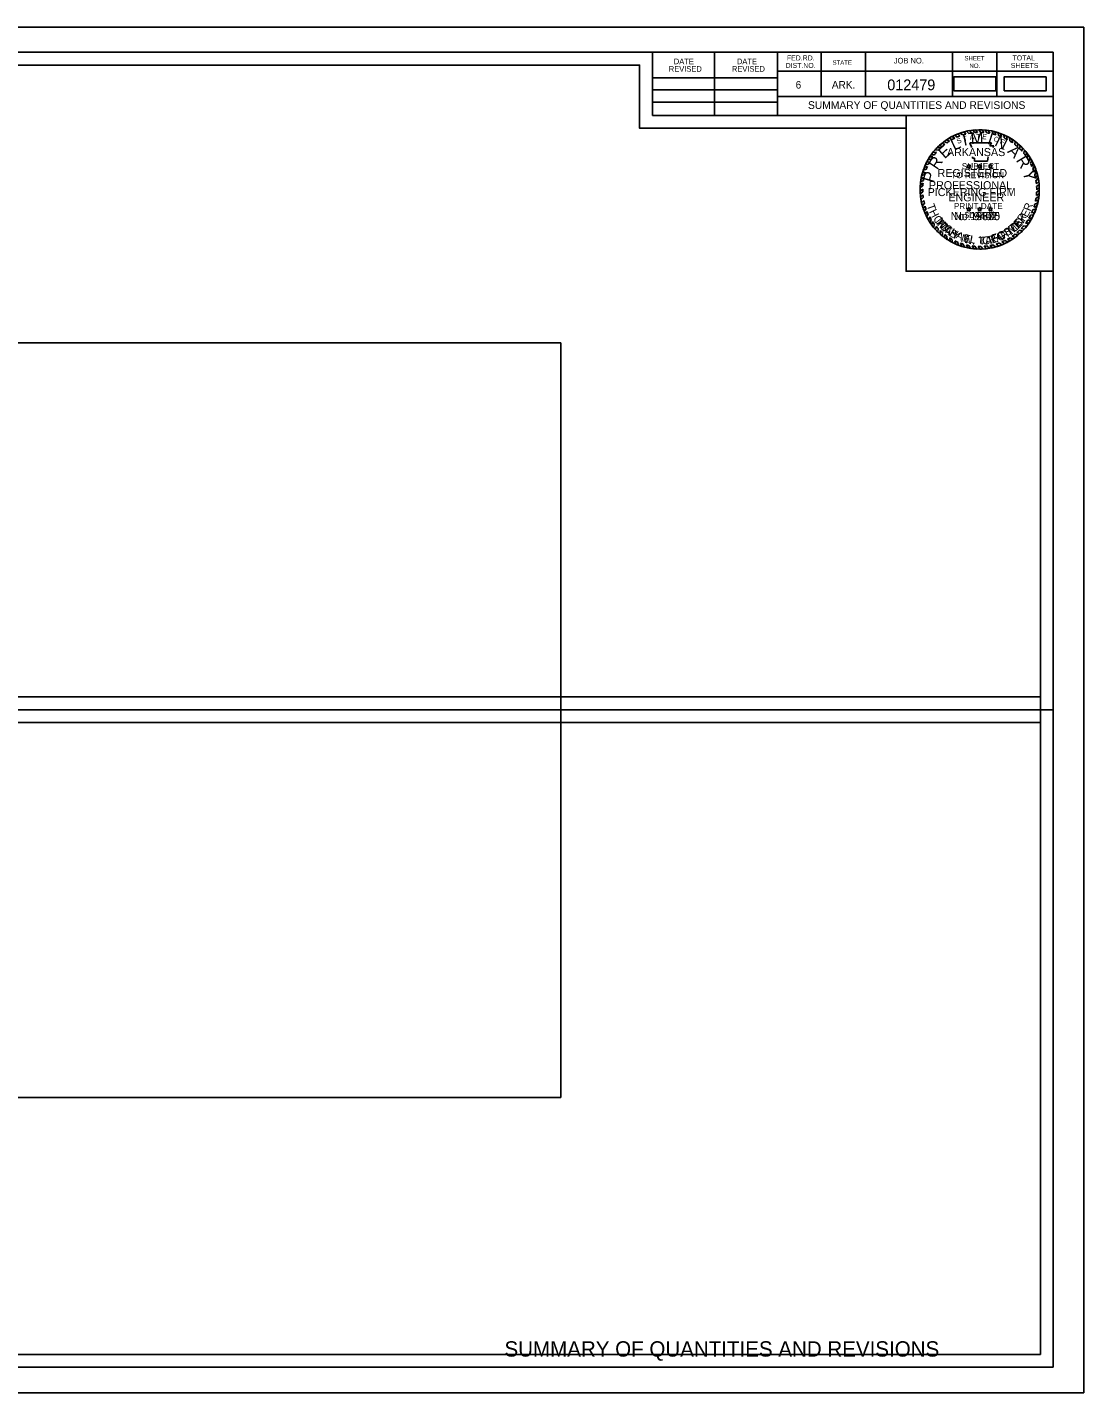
# Model space of a CAD drawing. Extents: x 1369290 to 1371547, y 379683 to 379897.
# Drawn here: x 1371381.5 to 1371546.5, y 379683.5 to 379896.8 of the extents above; entities that cross this region are included whole.
import ezdxf

# ---------------------------------------------------------------- set-up
doc = ezdxf.new("R2010")
doc.units = 0
for name, color, linetype in [('Default', 7, 'Continuous'), ('R_Border', 7, 'Continuous'), ('R_Border Notes', 7, 'Continuous'), ('R_Border Plan-Plan', 7, 'Continuous'), ('R_Border Title', 7, 'Continuous'), ('R_No Plot', 7, 'Continuous'), ('STAMP_PE_CRAFTON', 7, 'Continuous'), ('STAMP_PE_FOSTER', 7, 'Continuous'), ('STAMP_PE_SEAL-INFO', 7, 'Continuous'), ('STAMP_PE_TAEGTMEYER', 7, 'Continuous'), ('STAMP_PE_TXT', 7, 'Continuous'), ('STAMP_PRELIMINARY', 7, 'Continuous')]:
    doc.layers.add(name, color=color, linetype=linetype)

msp = doc.modelspace()

# ---------------------------------------------------------------- linework, layer by layer
at = {"layer": 'Default'}
for points in [[(1371526.23, 379886.89), (1371532.79, 379886.89), (1371532.79, 379889.08), (1371526.23, 379889.08)], [(1371534.1, 379886.89), (1371540.66, 379886.89), (1371540.66, 379889.08), (1371534.1, 379889.08)], [(1371294.91, 379729.63), (1371464.81, 379729.63), (1371464.81, 379847.52), (1371294.91, 379847.52)]]:
    msp.add_lwpolyline(points, close=True, dxfattribs=at)
at = {"layer": 'R_Border'}
for p, q in [((1371225.6, 379892.93), (1371541.78, 379892.93)), ((1371479.14, 379883.05), (1371479.14, 379892.93)), ((1371488.82, 379883.05), (1371488.82, 379892.93)), ((1371498.68, 379892.93), (1371498.68, 379883.05)), ((1371505.52, 379892.93), (1371505.52, 379885.99)), ((1371512.46, 379892.93), (1371512.46, 379885.99)), ((1371526.04, 379892.93), (1371526.04, 379885.99)), ((1371532.98, 379892.93), (1371532.98, 379885.99)), ((1371541.78, 379687.47), (1371541.78, 379892.93)), ((1371479.14, 379888.91), (1371498.68, 379888.91)), ((1371541.78, 379889.99), (1371498.68, 379889.99)), ((1371541.78, 379890.01), (1371541.78, 379890.01)), ((1371479.14, 379887.05), (1371498.68, 379887.05)), ((1371479.14, 379885.11), (1371498.68, 379885.11)), ((1371541.78, 379885.99), (1371498.68, 379885.99)), ((1371501.64, 379885.99), (1371541.78, 379885.99)), ((1371541.78, 379883.05), (1371479.14, 379883.05)), ((1371541.78, 379687.47), (1371225.6, 379687.47))]:
    msp.add_line(p, q, dxfattribs=at)
at = {"layer": 'R_Border Plan-Plan'}
msp.add_line((1371225.6, 379790.2), (1371541.78, 379790.2), dxfattribs=at)
at = {"layer": 'R_No Plot'}
for points in [[(1371213.19, 379896.82), (1371546.53, 379896.82), (1371546.53, 379683.48), (1371213.19, 379683.48)], [(1371539.78, 379792.2), (1371227.6, 379792.2), (1371227.6, 379890.93), (1371477.14, 379890.93), (1371477.14, 379881.05), (1371494.68, 379881.05), (1371518.78, 379881.05), (1371518.78, 379858.71), (1371539.78, 379858.71)], [(1371227.6, 379890.93), (1371477.14, 379890.93), (1371477.14, 379881.05), (1371494.68, 379881.05), (1371518.78, 379881.05), (1371518.78, 379858.71), (1371539.78, 379858.71), (1371539.78, 379689.47), (1371227.6, 379689.47)], [(1371518.78, 379883.05), (1371541.78, 379883.05), (1371541.78, 379858.71), (1371518.78, 379858.71)], [(1371227.6, 379788.2), (1371539.78, 379788.2), (1371539.78, 379689.47), (1371227.6, 379689.47)]]:
    msp.add_lwpolyline(points, close=True, dxfattribs=at)
at = {"layer": 'STAMP_PE_SEAL-INFO'}
for p, q in [((1371525.95, 379879.75), (1371526.42, 379879.52)), ((1371526.38, 379879.96), (1371526.77, 379879.68)), ((1371526.89, 379880.18), (1371527.19, 379879.85)), ((1371527.24, 379880.3), (1371527.62, 379880)), ((1371527.83, 379880.49), (1371528.12, 379880.14)), ((1371528.22, 379880.58), (1371528.57, 379880.24)), ((1371528.7, 379880.68), (1371529, 379880.31)), ((1371529.22, 379880.75), (1371529.5, 379880.37)), ((1371529.95, 379880.4), (1371529.64, 379880.79)), ((1371530.45, 379880.4), (1371530.17, 379880.81)), ((1371530.91, 379880.38), (1371530.65, 379880.81)), ((1371531.41, 379880.33), (1371531.12, 379880.77)), ((1371531.84, 379880.27), (1371531.58, 379880.72)), ((1371532.4, 379880.15), (1371532.23, 379880.61)), ((1371532.8, 379880.04), (1371532.64, 379880.51)), ((1371533.26, 379879.89), (1371533.11, 379880.37)), ((1371533.67, 379879.73), (1371533.53, 379880.23)), ((1371534.13, 379879.53), (1371534.03, 379880.02)), ((1371534.58, 379879.3), (1371534.49, 379879.81)), ((1371523.32, 379877.69), (1371523.84, 379877.65)), ((1371523.64, 379878.04), (1371524.19, 379877.99)), ((1371523.98, 379878.36), (1371524.44, 379878.22)), ((1371524.32, 379878.66), (1371524.85, 379878.56)), ((1371524.7, 379878.99), (1371525.15, 379878.78)), ((1371525.12, 379879.25), (1371525.56, 379879.05)), ((1371525.51, 379879.5), (1371525.94, 379879.27)), ((1371528.75, 379878.78), (1371532.1, 379878.78)), ((1371528.87, 379878.47), (1371528.75, 379878.78)), ((1371528.98, 379878.18), (1371528.87, 379878.47)), ((1371528.99, 379878.06), (1371528.98, 379878.18)), ((1371532.1, 379878.78), (1371531.87, 379878.29)), ((1371531.87, 379878.29), (1371532.51, 379878.29)), ((1371532.51, 379878.29), (1371532.36, 379878.06)), ((1371534.97, 379879.07), (1371534.93, 379879.57)), ((1371535.4, 379878.78), (1371535.37, 379879.3)), ((1371535.76, 379878.52), (1371535.8, 379879)), ((1371536.21, 379878.15), (1371536.23, 379878.67)), ((1371536.52, 379877.85), (1371536.59, 379878.35)), ((1371536.88, 379877.48), (1371536.95, 379878.01)), ((1371537.16, 379877.16), (1371537.29, 379877.63)), ((1371521.8, 379875.35), (1371522.3, 379875.46)), ((1371521.98, 379875.74), (1371522.48, 379875.81)), ((1371522.22, 379876.17), (1371522.7, 379876.19)), ((1371522.46, 379876.57), (1371522.98, 379876.6)), ((1371522.7, 379876.91), (1371523.2, 379876.91)), ((1371522.97, 379877.28), (1371523.52, 379877.3)), ((1371529.18, 379876.35), (1371529.15, 379876.57)), ((1371529.49, 379876.35), (1371529.18, 379876.35)), ((1371529.49, 379875.92), (1371529.49, 379876.35)), ((1371531.52, 379875.92), (1371529.49, 379875.92)), ((1371531.54, 379876.26), (1371531.52, 379875.92)), ((1371531.61, 379876.57), (1371531.54, 379876.26)), ((1371537.48, 379876.75), (1371537.61, 379877.25)), ((1371537.7, 379876.43), (1371537.88, 379876.89)), ((1371538.01, 379875.93), (1371538.19, 379876.42)), ((1371538.21, 379875.57), (1371538.43, 379876.01)), ((1371538.44, 379875.08), (1371538.66, 379875.57)), ((1371521.56, 379873.36), (1371521.1, 379873.11)), ((1371521.2, 379873.6), (1371521.67, 379873.8)), ((1371521.31, 379874.01), (1371521.78, 379874.18)), ((1371521.46, 379874.51), (1371521.95, 379874.65)), ((1371521.61, 379874.92), (1371522.12, 379875.07)), ((1371538.58, 379874.75), (1371538.84, 379875.18)), ((1371538.77, 379874.2), (1371539.04, 379874.67)), ((1371538.88, 379873.83), (1371539.17, 379874.28)), ((1371539.01, 379873.27), (1371539.33, 379873.72)), ((1371539.08, 379872.89), (1371539.44, 379873.25)), ((1371521.38, 379872.04), (1371520.96, 379871.78)), ((1371521.37, 379871.55), (1371520.96, 379871.21)), ((1371521.42, 379872.46), (1371520.98, 379872.18)), ((1371521.37, 379871.14), (1371520.98, 379870.81)), ((1371521.48, 379872.9), (1371521.03, 379872.68)), ((1371539.15, 379872.38), (1371539.52, 379872.72)), ((1371539.18, 379871.97), (1371539.57, 379872.26)), ((1371539.18, 379871.04), (1371539.6, 379871.32)), ((1371539.19, 379871.45), (1371539.6, 379871.77)), ((1371521.41, 379870.64), (1371521.04, 379870.29)), ((1371521.46, 379870.21), (1371521.1, 379869.84)), ((1371521.54, 379869.75), (1371521.2, 379869.39)), ((1371521.63, 379869.34), (1371521.32, 379868.92)), ((1371538.89, 379869.2), (1371539.37, 379869.4)), ((1371539, 379869.65), (1371539.46, 379869.84)), ((1371539.09, 379870.15), (1371539.54, 379870.37)), ((1371539.14, 379870.54), (1371539.58, 379870.79)), ((1371521.76, 379868.89), (1371521.46, 379868.47)), ((1371521.9, 379868.47), (1371521.61, 379868.05)), ((1371522.06, 379868.04), (1371521.8, 379867.62)), ((1371522.23, 379867.66), (1371522.01, 379867.19)), ((1371522.47, 379867.2), (1371522.28, 379866.71)), ((1371537.96, 379866.97), (1371538.47, 379867.03)), ((1371538.24, 379867.47), (1371538.73, 379867.54)), ((1371538.4, 379867.81), (1371538.89, 379867.9)), ((1371538.61, 379868.32), (1371539.09, 379868.45)), ((1371538.75, 379868.7), (1371539.24, 379868.9)), ((1371522.7, 379866.79), (1371522.52, 379866.32)), ((1371522.91, 379866.48), (1371522.8, 379865.93)), ((1371523.19, 379866.09), (1371523.09, 379865.56)), ((1371523.49, 379865.71), (1371523.4, 379865.19)), ((1371523.79, 379865.38), (1371523.73, 379864.85)), ((1371524.12, 379865.05), (1371524.09, 379864.52)), ((1371524.46, 379864.74), (1371524.46, 379864.21)), ((1371536.1, 379864.74), (1371536.57, 379864.61)), ((1371536.51, 379865.11), (1371536.95, 379864.97)), ((1371536.76, 379865.37), (1371537.24, 379865.29)), ((1371537.15, 379865.8), (1371537.61, 379865.73)), ((1371537.45, 379866.2), (1371537.96, 379866.2)), ((1371537.79, 379866.69), (1371538.27, 379866.69)), ((1371524.82, 379864.44), (1371524.84, 379863.92)), ((1371525.16, 379864.19), (1371525.2, 379863.68)), ((1371525.59, 379863.91), (1371525.65, 379863.4)), ((1371525.94, 379863.71), (1371526.03, 379863.19)), ((1371526.42, 379863.46), (1371526.57, 379862.94)), ((1371526.79, 379863.29), (1371526.96, 379862.78)), ((1371527.28, 379863.1), (1371527.49, 379862.59)), ((1371527.69, 379862.96), (1371527.92, 379862.47)), ((1371528.2, 379862.82), (1371528.41, 379862.36)), ((1371528.6, 379862.74), (1371528.84, 379862.28)), ((1371529.1, 379862.66), (1371529.34, 379862.21)), ((1371529.53, 379862.61), (1371529.81, 379862.18)), ((1371530.02, 379862.58), (1371530.32, 379862.17)), ((1371530.48, 379862.58), (1371530.82, 379862.18)), ((1371531, 379862.61), (1371531.32, 379862.23)), ((1371531.44, 379862.65), (1371531.81, 379862.29)), ((1371531.88, 379862.72), (1371532.27, 379862.38)), ((1371532.37, 379862.83), (1371532.75, 379862.5)), ((1371532.83, 379862.95), (1371533.25, 379862.65)), ((1371533.33, 379863.11), (1371533.77, 379862.84)), ((1371533.75, 379863.28), (1371534.17, 379863.02)), ((1371534.2, 379863.49), (1371534.69, 379863.28)), ((1371534.61, 379863.7), (1371535.03, 379863.47)), ((1371535.03, 379863.95), (1371535.48, 379863.75)), ((1371535.37, 379864.17), (1371535.81, 379863.98)), ((1371535.83, 379864.52), (1371536.3, 379864.37))]:
    msp.add_line(p, q, dxfattribs=at)
for radius, start, end in [(9.32, 117.6544, 120.8099), (9.32, 111.3124, 114.7026), (8.91, 110.3086, 113.1659), (9.32, 105.2339, 109.0352), (8.91, 104.0352, 107.3615), (9.32, 99.7525, 102.7765), (8.91, 98.258, 101.0329), (9.32, 93.9381, 96.5517), (8.91, 92.1102, 95.0367), (9.32, 87.7298, 90.6707), (8.91, 85.9628, 88.9097), (9.32, 81.9732, 84.8236), (8.91, 79.9264, 82.696), (9.32, 75.3125, 77.9426), (8.91, 73.5575, 76.2314), (9.32, 69.6061, 72.3058), (8.91, 67.6248, 70.504), (9.32, 63.1329, 66.2704), (9.32, 135.4021, 138.3031), (8.91, 133.1331, 136.2562), (9.32, 129.7326, 132.5376), (8.91, 127.5297, 130.9683), (9.32, 123.6199, 126.5906), (8.91, 121.9746, 125.11), (8.91, 115.6869, 119.1583), (8.91, 61.1558, 64.3784), (9.32, 56.9003, 60.0942), (8.91, 54.9238, 58.2702), (8.91, 48.3016, 52.0395), (9.32, 50.3492, 53.7159), (8.91, 42.2212, 45.5512), (9.32, 44.3405, 47.3929), (9.32, 38.1247, 41.2316), (9.32, 152.864, 155.5189), (9.32, 147.0072, 149.899), (8.91, 151.0315, 153.573), (9.32, 141.6056, 144.4486), (8.91, 145.0197, 148.2104), (8.91, 139.301, 142.5873), (8.91, 36.135, 39.5311), (8.91, 29.9032, 33.6645), (9.32, 31.9614, 35.4294), (8.91, 23.7732, 27.2211), (9.32, 25.9391, 29.0125), (9.32, 164.3068, 166.894), (9.32, 158.4077, 161.0701), (8.91, 167.9048, 170.9039), (8.91, 162.4331, 165.0013), (8.91, 156.3402, 159.2319), (8.91, 17.6802, 21.4251), (9.32, 19.9538, 23.3141), (8.91, 11.5444, 15.2364), (9.32, 13.8421, 17.4447), (9.32, 7.5852, 10.8621), (9.32, 175.7409, 178.2066), (9.32, 181.7251, 184.1626), (9.32, 170.0003, 172.6878), (8.91, 179.6454, 182.2633), (8.91, 173.73, 176.4734), (8.91, 5.7599, 9.0606), (8.91, 359.7329, 3.0639), (9.32, 1.7215, 4.7268), (9.32, 355.7156, 358.9569), (9.32, 187.4204, 190.1927), (9.32, 193.0369, 195.9973), (8.91, 185.4539, 188.234), (8.91, 191.2274, 193.9858), (8.91, 341.777, 345.0925), (8.91, 348.0778, 351.3435), (8.91, 353.8632, 357.1274), (9.32, 343.8925, 347.035), (9.32, 349.8305, 353.0885), (9.32, 198.8967, 201.6281), (8.91, 196.9675, 199.8353), (9.32, 204.5479, 207.4328), (8.91, 202.7761, 205.4791), (8.91, 208.7883, 211.7934), (8.91, 329.5549, 333.2076), (8.91, 335.6038, 339.1858), (9.32, 331.4037, 334.9332), (9.32, 337.3837, 340.9933), (9.32, 210.8636, 213.6571), (9.32, 216.6115, 219.491), (8.91, 214.1838, 217.2747), (9.32, 222.48, 225.3801), (8.91, 220.3909, 223.3056), (8.91, 226.2494, 229.2407), (8.91, 310.7744, 314.3161), (9.32, 312.4518, 315.6633), (8.91, 316.6531, 320.3711), (9.32, 318.2846, 321.8043), (8.91, 323.5851, 327.4407), (9.32, 325.4405, 328.9872), (9.32, 228.3665, 231.348), (8.91, 232.229, 234.9336), (9.32, 234.295, 236.9452), (8.91, 238.2223, 240.8353), (9.32, 240.1977, 242.8613), (8.91, 244.3204, 246.9486), (9.32, 246.576, 249.1558), (8.91, 250.3491, 253.1216), (9.32, 252.5967, 255.3252), (8.91, 256.505, 259.1192), (8.91, 262.3783, 265.2012), (8.91, 268.3215, 271.277), (8.91, 274.6157, 277.4486), (8.91, 280.3459, 283.5814), (8.91, 286.6423, 289.9783), (9.32, 288.5709, 291.9733), (8.91, 292.8745, 296.1185), (9.32, 294.6481, 298.2166), (8.91, 299.0768, 302.1724), (9.32, 300.621, 303.8703), (8.91, 304.823, 308.5143), (9.32, 306.3721, 310.208), (9.32, 258.4433, 261.1398), (9.32, 264.1978, 267.1009), (9.32, 270.2548, 273.3361), (9.32, 276.4239, 279.4357), (9.32, 282.3199, 285.3702)]:
    msp.add_arc((1371530.28, 379871.49), radius, start, end, dxfattribs=at)
at = {"layer": 'STAMP_PE_TXT'}
for p, q in [((1371528.51, 379875.21), (1371528.58, 379875.44)), ((1371528.58, 379875.44), (1371528.66, 379875.21)), ((1371530.2, 379875.21), (1371530.28, 379875.44)), ((1371530.28, 379875.44), (1371530.36, 379875.21)), ((1371531.9, 379875.21), (1371531.98, 379875.44)), ((1371531.98, 379875.44), (1371532.05, 379875.21)), ((1371528.46, 379875.06), (1371528.26, 379875.21)), ((1371528.26, 379875.21), (1371528.51, 379875.21)), ((1371528.38, 379874.83), (1371528.46, 379875.06)), ((1371528.58, 379874.97), (1371528.38, 379874.83)), ((1371528.78, 379874.83), (1371528.58, 379874.97)), ((1371528.66, 379875.21), (1371528.9, 379875.21)), ((1371528.9, 379875.21), (1371528.71, 379875.06)), ((1371528.71, 379875.06), (1371528.78, 379874.83)), ((1371530.16, 379875.06), (1371529.96, 379875.21)), ((1371529.96, 379875.21), (1371530.2, 379875.21)), ((1371530.08, 379874.83), (1371530.16, 379875.06)), ((1371530.28, 379874.97), (1371530.08, 379874.83)), ((1371530.48, 379874.83), (1371530.28, 379874.97)), ((1371530.36, 379875.21), (1371530.6, 379875.21)), ((1371530.6, 379875.21), (1371530.4, 379875.06)), ((1371530.4, 379875.06), (1371530.48, 379874.83)), ((1371531.86, 379875.06), (1371531.66, 379875.21)), ((1371531.66, 379875.21), (1371531.9, 379875.21)), ((1371531.78, 379874.83), (1371531.86, 379875.06)), ((1371531.98, 379874.97), (1371531.78, 379874.83)), ((1371532.18, 379874.83), (1371531.98, 379874.97)), ((1371532.05, 379875.21), (1371532.3, 379875.21)), ((1371532.3, 379875.21), (1371532.1, 379875.06)), ((1371532.1, 379875.06), (1371532.18, 379874.83)), ((1371528.46, 379868.35), (1371528.26, 379868.5)), ((1371528.26, 379868.5), (1371528.51, 379868.5)), ((1371528.38, 379868.12), (1371528.46, 379868.35)), ((1371528.58, 379868.27), (1371528.38, 379868.12)), ((1371528.51, 379868.5), (1371528.58, 379868.73)), ((1371528.58, 379868.73), (1371528.66, 379868.5)), ((1371528.78, 379868.12), (1371528.58, 379868.27)), ((1371528.66, 379868.5), (1371528.9, 379868.5)), ((1371528.9, 379868.5), (1371528.71, 379868.35)), ((1371528.71, 379868.35), (1371528.78, 379868.12)), ((1371530.16, 379868.35), (1371529.96, 379868.5)), ((1371529.96, 379868.5), (1371530.2, 379868.5)), ((1371530.08, 379868.12), (1371530.16, 379868.35)), ((1371530.28, 379868.27), (1371530.08, 379868.12)), ((1371530.2, 379868.5), (1371530.28, 379868.73)), ((1371530.28, 379868.73), (1371530.36, 379868.5)), ((1371530.48, 379868.12), (1371530.28, 379868.27)), ((1371530.36, 379868.5), (1371530.6, 379868.5)), ((1371530.6, 379868.5), (1371530.4, 379868.35)), ((1371530.4, 379868.35), (1371530.48, 379868.12)), ((1371531.86, 379868.35), (1371531.66, 379868.5)), ((1371531.66, 379868.5), (1371531.9, 379868.5)), ((1371531.78, 379868.12), (1371531.86, 379868.35)), ((1371531.98, 379868.27), (1371531.78, 379868.12)), ((1371531.9, 379868.5), (1371531.98, 379868.73)), ((1371531.98, 379868.73), (1371532.05, 379868.5)), ((1371532.18, 379868.12), (1371531.98, 379868.27)), ((1371532.05, 379868.5), (1371532.3, 379868.5)), ((1371532.3, 379868.5), (1371532.1, 379868.35)), ((1371532.1, 379868.35), (1371532.18, 379868.12))]:
    msp.add_line(p, q, dxfattribs=at)
at = {"layer": 'STAMP_PRELIMINARY'}
msp.add_circle((1371530.28, 379871.49), 9.32, dxfattribs=at)

# ---------------------------------------------------------------- texts
at = {"layer": 'R_Border'}
for s, height, p in [('FED.RD.', 0.782, (1371500.16, 379891.65)), ('TOTAL', 0.782, (1371535.42, 379891.65)), ('REVISED', 0.879, (1371481.7, 379889.88)), ('DATE', 0.879, (1371482.48, 379891.06)), ('REVISED', 0.879, (1371491.56, 379889.88)), ('DATE', 0.879, (1371492.34, 379891.06)), ('DIST.NO.', 0.782, (1371499.96, 379890.47)), ('STATE', 0.684, (1371507.28, 379890.97)), ('JOB NO.', 0.879, (1371516.86, 379891.17)), ('SHEET', 0.684, (1371527.9, 379891.65)), ('NO.', 0.684, (1371528.68, 379890.47)), ('SHEETS', 0.782, (1371535.14, 379890.47)), ('6', 1.17, (1371501.52, 379887.25)), ('ARK.', 1.172, (1371507.18, 379887.25))]:
    msp.add_text(s, height=height, dxfattribs=at).set_placement(p)
at = {"layer": 'R_Border Notes'}
for s, height, p in [('012479', 1.68, (1371515.84, 379886.99)), ('SUMMARY OF QUANTITIES AND REVISIONS', 1.2, (1371503.45, 379884.07))]:
    msp.add_text(s, height=height, dxfattribs=at).set_placement(p)
at = {"layer": 'R_Border Title'}
msp.add_text('SUMMARY OF QUANTITIES AND REVISIONS', height=2.4, dxfattribs=at).set_placement((1371456.02, 379689.12))
at = {"layer": 'STAMP_PE_CRAFTON'}
for s, rotation, p in [('T', 310.7442, (1371523.25, 379866.39)), ('N', 49.2411, (1371536.56, 379865.51)), ('O', 317.6422, (1371523.91, 379865.58)), ('N', 324.4537, (1371524.76, 379864.79)), ('Y', 331.1686, (1371525.79, 379864.08)), ('F', 28.7821, (1371533.94, 379863.62)), ('T', 34.1136, (1371534.86, 379864.13)), ('O', 41.8391, (1371535.72, 379864.73)), ('N', 347.4752, (1371527.85, 379863.16)), ('.', 356.8926, (1371529.08, 379862.88)), ('C', 6.0117, (1371530.75, 379862.83)), ('R', 14.8189, (1371531.85, 379862.95)), ('A', 20.5125, (1371532.96, 379863.25))]:
    msp.add_text(s, height=1.25, rotation=rotation, dxfattribs=at).set_placement(p)
msp.add_text('No. 12370', height=1.25, dxfattribs=at).set_placement((1371525.74, 379866.69))
at = {"layer": 'STAMP_PE_FOSTER'}
for s, rotation, p in [('M', 308.339, (1371523.4, 379866.51)), ('E', 46.9613, (1371536.28, 379865.48)), ('R', 54.5031, (1371537, 379866.3)), ('I', 314.1842, (1371524.19, 379865.57)), ('C', 319.8733, (1371524.55, 379865.22)), ('H', 327.7235, (1371525.48, 379864.48)), ('A', 335.7276, (1371526.46, 379863.9)), ('O', 23.719, (1371533.36, 379863.57)), ('S', 31.7234, (1371534.47, 379864.1)), ('T', 39.4194, (1371535.42, 379864.73)), ('E', 343.5779, (1371527.6, 379863.43)), ('L', 350.8115, (1371528.65, 379863.16)), ('L', 1.2666, (1371530.19, 379863)), ('.', 6.8035, (1371531.24, 379863.06)), ('F', 15.8691, (1371532.32, 379863.24))]:
    msp.add_text(s, height=1.2, rotation=rotation, dxfattribs=at).set_placement(p)
msp.add_text('No. 9402', height=1.25, dxfattribs=at).set_placement((1371526.27, 379866.69))
at = {"layer": 'STAMP_PE_TAEGTMEYER'}
for s, rotation, p in [('T', 289.646, (1371521.97, 379869)), ('R', 69.57, (1371538.23, 379868)), ('H', 296.7339, (1371522.33, 379868.02)), ('O', 303.7708, (1371522.93, 379866.91)), ('E', 46.8094, (1371536.32, 379865.27)), ('Y', 53.9986, (1371537.06, 379866.08)), ('E', 63.0984, (1371537.73, 379867.02)), ('M', 314.2033, (1371523.58, 379865.96)), ('A', 321.0594, (1371524.54, 379864.99)), ('S', 327.8239, (1371525.37, 379864.35)), ('G', 23.3052, (1371533.28, 379863.35)), ('T', 31.466, (1371534.38, 379863.84)), ('M', 39.3, (1371535.28, 379864.39)), ('N', 344.2727, (1371527.27, 379863.34)), ('.', 350.6464, (1371528.48, 379863.01)), ('T', 3.0061, (1371530.14, 379862.81)), ('A', 8.9826, (1371531.19, 379862.87)), ('E', 17.6836, (1371532.23, 379863.02))]:
    msp.add_text(s, height=1.25, rotation=rotation, dxfattribs=at).set_placement(p)
msp.add_text('No. 19605', height=1.25, dxfattribs=at).set_placement((1371525.74, 379866.69))
at = {"layer": 'STAMP_PE_TXT'}
for s, rotation, p in [('T', 16.311, (1371527.8, 379878.97)), ('A', 9.0679, (1371528.76, 379879.22)), ('T', 1.8248, (1371529.75, 379879.35)), ('E', 355.2002, (1371530.66, 379879.36)), ('O', 342.2506, (1371532.39, 379879.08)), ('S', 23.5541, (1371526.88, 379878.59)), ('F', 335.0075, (1371533.35, 379878.74))]:
    msp.add_text(s, height=0.781, rotation=rotation, dxfattribs=at).set_placement(p)
for s, p in [('ARKANSAS', (1371525.17, 379876.7)), ('REGISTERED', (1371523.7, 379873.43)), ('PROFESSIONAL', (1371522.35, 379871.53)), ('ENGINEER', (1371525.39, 379869.63))]:
    msp.add_text(s, height=1.25, dxfattribs=at).set_placement(p)
at = {"layer": 'STAMP_PRELIMINARY'}
for s, rotation, p in [('I', 12.5248, (1371527.82, 379878.28)), ('M', 3.1074, (1371528.92, 379878.59)), ('I', 342.3164, (1371531.38, 379878.65)), ('N', 333.9382, (1371532.49, 379878.38)), ('E', 42.3578, (1371524.81, 379876.19)), ('L', 25.513, (1371526.29, 379877.52)), ('A', 315.6579, (1371534.53, 379877.35)), ('R', 56.2292, (1371523.65, 379874.45)), ('R', 301.3831, (1371535.89, 379876.04)), ('P', 73.913, (1371523.1, 379872.43)), ('Y', 283.2593, (1371536.98, 379874.25))]:
    msp.add_text(s, height=1.8, rotation=rotation, dxfattribs=at).set_placement(p)
for s, height, p in [('SUBJECT', 0.96, (1371527.48, 379874.64)), ('TO REVISION', 0.96, (1371525.82, 379873.25)), ('PICKERING FIRM', 1.25, (1371522.15, 379870.45)), ('PRINT DATE', 0.96, (1371526.24, 379868.41)), ('$DATE$', 0.96, (1371527.91, 379867.02))]:
    msp.add_text(s, height=height, dxfattribs=at).set_placement(p)

doc.saveas('drawing.dxf')
